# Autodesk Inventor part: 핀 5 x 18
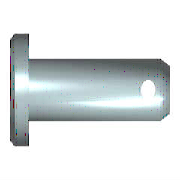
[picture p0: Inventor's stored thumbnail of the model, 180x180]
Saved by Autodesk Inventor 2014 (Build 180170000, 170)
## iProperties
Created: 2012-02
Part Number: 핀 5 x 18
Material: 강철
Description: 머리가 있는 클레비스 핀
Document SubType Name: Modeling
Standard: ISO 2341
Designer: test
Standard Revision: Second edition 1986-11-01
Standards Organization: ISO
Language: ko-KR
Size Designation: B - 5 x 18
Categories: <MemberInstance><Categories><Category DisplayName="조임쇠" InternalName="e4da775c-781d-43d5-af7c-5136215cf5a6" Mnemonic="FSTN"><Category DisplayName="핀" InternalNa
Density: 7.85 g/cm^3
Appearance: 강철
Mass: 3.15068 g
Surface Area: 4.06263 cm^2
Volume: 0.40136 cm^3
IsCustomPart: 1
Author: test
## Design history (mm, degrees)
sketch "스케치1"
  geometry: L1 (-1.6, 0)-(-1.6, 4); L2 (-1.6, 4)-(0, 4); L3 (0, 4)-(0, 2.5); L4 (0, 2.5)-(18, 2.5); L5 (18, 2.5)-(18, 0); L6 (-1.6, 0)-(18, 0); L7 (-4, 0)-(17, 0) reference; L8 (0, -0.98)-(0, 3.08) reference; C1 r 0.6 at (15.1, 0)
  constraints: 12 end point, 3 parallel, 2 collinear, 2 perpendicular, 1 centre point, 1 point on line, 1 vertical
  dimensions: "d0" = 5 diameter of L4 L6 (= NND); "d1" = 8 diameter of L2 L6 (= KOD); "d2" = 1.6 distance of L1.end L2.end (= KOH); "d3" = 18 distance of L3.end L4.end (= NLG); "d5" = 2.9 distance from line of L5 C1.centre (= DIST); "d6" = 1.2 diameter of C1 (= BOR)
revolve "본체" stored, may be unused: angle "d4" = 90 deg
extrude "구멍" cut sketch "스케치1" stored distance "d7" = 5 (= NND); taper "d8" = 0 deg
workaxis "Work Axis1"
workplane "Work Plane1"
body "Solid1"
chamfer "모따기1" distance "d9" = 1 (= PHH2); stored, may be unused: angle "d10" = 45 deg (= FAWI2), second distance "d16" = 1 (= PHH2)
chamfer "모따기2" distance "d11" = 2 (= PHH1); stored, may be unused: angle "d12" = 30 deg (= FAWI1), second distance "d17" = 2 (= PHH1)
other parameters: "PHH1" = 2 [user parameter; used in 2 equation terms], "PHH2" = 1 [user parameter; used in 2 equation terms], "KOD" = 8 [user parameter; used in 1 equation term], "KOH" = 1.6 [user parameter; used in 1 equation term], "NND" = 5 [user parameter; used in 2 equation terms], "FAWI1" = 30 deg [user parameter; used in 1 equation term], "FAWI2" = 45 deg [user parameter; used in 1 equation term], "DIST" = 2.9 [user parameter; used in 1 equation term], "BOR" = 1.2 [user parameter; used in 1 equation term], "NLG" = 18 [user parameter; used in 1 equation term], "d13" = 0, "d14" = 0, "d27" = 0, "d28" = 0, "d29" = 0, "d30" = 0, "d31" = 0
